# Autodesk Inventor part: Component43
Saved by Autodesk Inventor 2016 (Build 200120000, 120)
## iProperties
Created: 2016-09
Part Number: Component43
Material: Generic
Document SubType Name: Modeling
Designer: Administrator
Appearance: Generic
Author: Administrator
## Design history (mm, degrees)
feature "Body1"
body "Solid1"
